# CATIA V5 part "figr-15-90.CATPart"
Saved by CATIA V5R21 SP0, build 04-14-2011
Part number: Part1
Bounding box of the stored display mesh (mm): x -45.183 to 59.676, y -22.214 to 29.903, z -4 to 1
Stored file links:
  D:\CATIA V5R21 E-RESOURCES\CATIA-V5R21\catia-v5r21-prt\c15-catia-v5r20-prt\c15-catia-v5r21-figr-15-90.CATPart
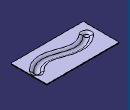
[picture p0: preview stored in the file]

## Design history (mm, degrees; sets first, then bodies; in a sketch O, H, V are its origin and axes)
SheetMetalParameters1: Thickness 1, BendRadius 5, KFactor 0.5 {= log(min(100,max(20*SheetMetalParameters1.BendRadius,SheetMetalParameters1.Thickness)/SheetMetalParameters1.Thickness))/log(100)/2}, ReliefRadialLength 1, ReliefAxialLength 2, MinimumBendRadius 0
Body1 (main body)
  Sketch1 on xy-plane, origin (0, 0, 0), H (1, 0, 0), V (0, 1, 0)
    line L1 (-45.1833, 29.903) -> (59.6761, 29.903)
    line L2 (59.6761, 29.903) -> (59.6761, -22.2137)
    line L3 (59.6761, -22.2137) -> (-45.1833, -22.2137)
    line L4 (-45.1833, -22.2137) -> (-45.1833, 29.903)
    horizontal: L1 H, L3 H
    vertical: L2 V, L4 V
  Wall1: Thickness 1, Profile Sketch1
  Sketch2 on face of Wall1, origin (0, 0, 1), H (1, 0, 0), V (0, 1, 0)
    spline S1 through (-31.3214, -3.7025) (-6.2947, 5.2247) (29.3365, -3.7025) (50.9697, 6.9251)
  d_Stamp1: Stamp_FilletRadius 4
